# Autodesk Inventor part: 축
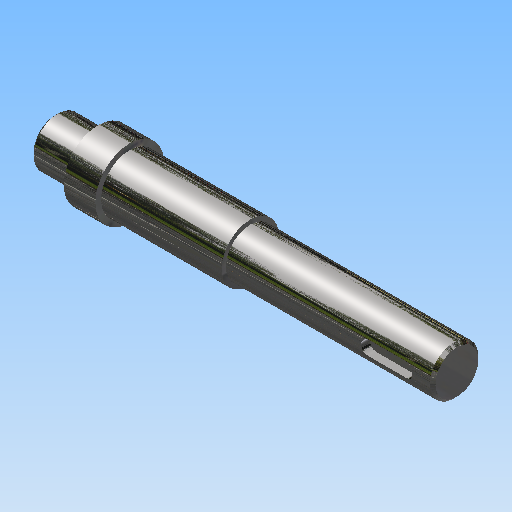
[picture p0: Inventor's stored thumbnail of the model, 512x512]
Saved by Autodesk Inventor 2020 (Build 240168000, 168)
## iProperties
Created: 2015-09
Part Number: 축
Material: 강철, 연강
Document SubType Name: Modeling
Designer: mduedu
Density: 7.86 g/cm^3
Mass: 263.424 g
Surface Area: 86.4309 cm^2
Volume: 33.5145 cm^3
Appearance: 반광택
Author: mduedu
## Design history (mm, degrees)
sketch "스케치1"
  geometry: L1 (-70, 0)-(70, 0); L2 (-70, 0)-(-70, 8.5); L3 (-70, 8.5)-(-55, 8.5); L4 (-55, 8.5)-(-55, 12); L5 (-55, 12)-(-44, 12); L6 (-44, 12)-(-44, 10); L7 (-44, 10)-(-2, 10); L8 (-2, 10)-(-2, 8.5); L9 (-2, 8.5)-(70, 8.5); L10 (70, 8.5)-(70, 0); 2 further points
  constraints: 20 end point, 5 parallel, 2 horizontal, 2 perpendicular, 1 coincident, 1 midpoint, 1 vertical
  dimensions: "d0" = 140 distance of L1.start L1.end; "d2" = 11 distance of L4.end L5.end; "d3" = 42 distance of L6.end L7.end; "d4" = 72 distance of L8.end L9.end; "d5" = 17 diameter of L3 L1; "d6" = 17 diameter of L9 L1; "d7" = 20 diameter of L7 L1; "d8" = 24 diameter of L5 L1
revolve "회전1" sketch "스케치1" stored, may be unused: angle "d9" = 90 deg
node "작업 평면1"
sketch "스케치2"
  geometry: L1 (13.5, 2.5)-(26.5, 2.5); L2 (26.5, -2.5)-(13.5, -2.5); L3 (13.5, 2.5)-(26.5, -2.5); L4 (26.5, 2.5)-(13.5, -2.5); L5 (36, -8.5)-(36, 8.5) reference; A1 r 2.5 centre (13.5, 0) between (13.5, 2.5) and (13.5, -2.5); A2 r 2.5 centre (26.5, 0) between (26.5, -2.5) and (26.5, 2.5); 2 further points
  constraints: 8 end point, 4 point on circle, 4 tangent, 2 centre point, 2 midpoint, 1 horizontal, 1 horizontal alignment, 1 parallel
  dimensions: "d10" = 18 dimension on A2 A1; "d12" = 7 distance edge to line of A2 L5; "d13" = 5 distance between parallel lines of L2 L1
extrude "돌출1" cut sketch "스케치2" distance "d14" = 3; taper "d15" = 0 deg
node "작업 평면2"
sketch "스케치4"
  geometry: L1 (7, -3)-(-9, -3); L2 (-9, 3)-(7, 3); L3 (-21, 10)-(-21, -10) reference; A1 r 3 centre (-9, 0) between (-9, 3) and (-9, -3); A2 r 3 centre (7, 0) between (7, -3) and (7, 3); 1 further point
  constraints: 4 end point, 4 point on circle, 4 tangent, 2 centre point, 1 horizontal, 1 horizontal alignment, 1 parallel
  dimensions: "d16" = 22 dimension on A1 A2; "d18" = 6 distance between parallel lines of L2 L1; "d19" = 9 distance edge to line of A1 L3
extrude "돌출2" cut sketch "스케치4" distance "d20" = 3.5; taper "d21" = 0 deg
sketch "스케치5"
  geometry: L1 (-2, 8.5)-(70, 8.5) reference; L2 (-2, -8.5)-(70, -8.5) reference; L3 (43, 8.5)-(43, -8.5); L4 (43, -6.5)-(41, -8.5); L5 (43, -8.5)-(41, -8.5); L6 (43, -8.5)-(43, -6.5); L7 (-2, -10)-(-2, 10) reference; 1 further point
  constraints: 8 end point, 4 point on line, 1 collinear, 1 perpendicular
  dimensions: "d22" = 4 diameter of L4.end L3; "d24" = 45 deg angle of L3 L4; "d26" = 45 distance between parallel lines of L3 L7
revolve "회전2" sketch "스케치5" stored, may be unused: angle "d27" = 90 deg
chamfer "모따기1" distance "d28" = 1; stored, may be unused: second distance "d29" = 2, angle "d30" = 45 deg
sketch "스케치6"
  geometry: L1 (43, -6.5)-(41, -8.5) reference; L2 (43, -6.5)-(45, -8.5) reference; 2 further points
  constraints: 1 coincident
node "솔리드1"
